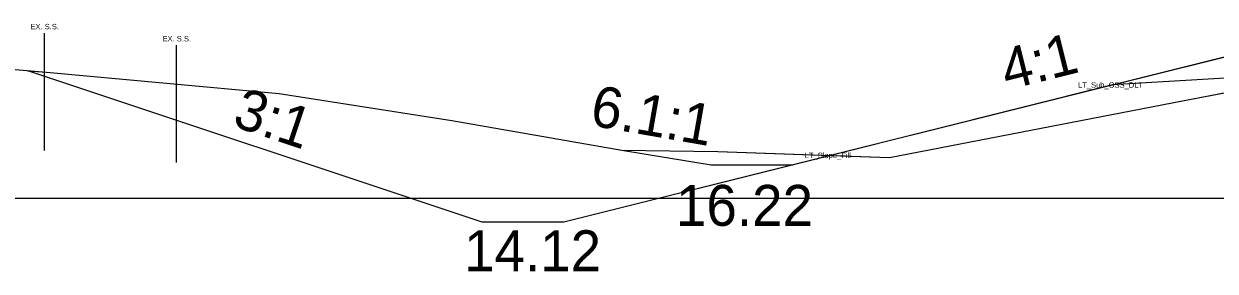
# Model space of a CAD drawing. Extents: x 2177029 to 2201446, y 59897 to 78390.
# Drawn here: x 2200119.31 to 2200162.97, y 64404.63 to 64413.7 of the extents above; entities that cross this region are included whole.
import ezdxf

# ---------------------------------------------------------------- set-up
doc = ezdxf.new("R2010")
doc.units = 0
for name, color, linetype in [('Exist Cross Section Cell', 7, 'Continuous'), ('Exist PHM Roadway Shape', 7, 'Continuous'), ('Exist XS Ground Line', 7, 'Continuous'), ('Old_Level_1', 7, 'Continuous'), ('Prop CMT Guardrail Widen Shoulder', 7, 'Continuous'), ('Prop CMT Pvmt Course 3', 7, 'Continuous'), ('Prop CMT Top Wall Envelope', 7, 'Continuous'), ('Prop Hatching', 7, 'Continuous'), ('Prop XS Earthwork Shape', 7, 'Continuous'), ('Prop XS Side Slope Text', 7, 'Continuous')]:
    doc.layers.add(name, color=color, linetype=linetype)

msp = doc.modelspace()

# ---------------------------------------------------------------- linework, layer by layer
at = {"layer": 'Exist Cross Section Cell'}
msp.add_line((2200042.732, 64407.31), (2200242.732, 64407.31), dxfattribs=at)
at = {"layer": 'Exist XS Ground Line'}
msp.add_lwpolyline([(2200113.261, 64412.508), (2200120.145, 64411.92), (2200128.668, 64411.14), (2200134.995, 64410.157), (2200141.22, 64409.061), (2200144.74, 64409.02), (2200151.028, 64408.798), (2200161.772, 64410.874), (2200167.852, 64412.04)], dxfattribs=at)
at = {"layer": 'Old_Level_1'}
for p, q in [((2200141.22, 64409.061), (2200144.494, 64408.528)), ((2200144.494, 64408.528), (2200147.494, 64408.528))]:
    msp.add_line(p, q, dxfattribs=at)
at = {"layer": 'Prop CMT Pvmt Course 3'}
msp.add_lwpolyline([(2200165.402, 64411.827), (2200159.203, 64411.455)], dxfattribs=at)
at = {"layer": 'Prop Hatching'}
for p, q in [((2200136.102, 64406.43), (2200119.457, 64411.979)), ((2200139.102, 64406.43), (2200136.102, 64406.43))]:
    msp.add_line(p, q, dxfattribs=at)
msp.add_lwpolyline([(2200166.466, 64412.891), (2200164.466, 64412.771), (2200139.102, 64406.43)], dxfattribs=at)
at = {"layer": 'Prop XS Earthwork Shape'}
for p, q in [((2200120.055, 64413.361), (2200120.055, 64409.053)), ((2200124.894, 64412.918), (2200124.894, 64408.61))]:
    msp.add_line(p, q, dxfattribs=at)
at = {"layer": 'Prop XS Side Slope Text'}
msp.add_lwpolyline([(2200165.402, 64411.827), (2200159.202, 64411.455), (2200164.466, 64412.771)], dxfattribs=at)
for points in [[(2200134.995, 64410.157), (2200141.22, 64409.061), (2200144.74, 64409.02), (2200148.877, 64408.874), (2200139.102, 64406.43), (2200136.102, 64406.43), (2200119.457, 64411.979), (2200120.145, 64411.92), (2200128.668, 64411.14)], [(2200165.402, 64411.827), (2200159.202, 64411.455), (2200148.877, 64408.874), (2200151.028, 64408.798), (2200161.772, 64410.874), (2200167.352, 64411.944)]]:
    msp.add_lwpolyline(points, close=True, dxfattribs=at)

# ---------------------------------------------------------------- texts
at = {"layer": 'Exist PHM Roadway Shape'}
for s, p in [('LT_Sub_OSS_DLT', (2200157.943, 64411.355)), ('LT_Slope_Fill', (2200147.928, 64408.774))]:
    msp.add_text(s, height=0.2, dxfattribs=at).set_placement(p)
at = {"layer": 'Old_Level_1'}
msp.add_text('6.1:1', height=1.5, rotation=350.0918, dxfattribs=at).set_placement((2200140.017, 64409.984))
msp.add_text('16.22', height=1.5, dxfattribs=at).set_placement((2200143.209, 64406.29))
at = {"layer": 'Prop CMT Guardrail Widen Shoulder'}
msp.add_text('4:1', height=1.5, rotation=14.0343, dxfattribs=at).set_placement((2200155.336, 64411.262))
at = {"layer": 'Prop CMT Top Wall Envelope'}
msp.add_text('3:1', height=1.5, rotation=341.5651, dxfattribs=at).set_placement((2200126.906, 64409.966))
msp.add_text('14.12', height=1.5, dxfattribs=at).set_placement((2200135.445, 64404.627))
at = {"layer": 'Prop XS Earthwork Shape'}
for p in [(2200119.557, 64413.496), (2200124.396, 64413.053)]:
    msp.add_text('EX. S.S.', height=0.2, dxfattribs=at).set_placement(p)

doc.saveas('drawing.dxf')
